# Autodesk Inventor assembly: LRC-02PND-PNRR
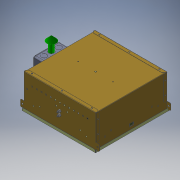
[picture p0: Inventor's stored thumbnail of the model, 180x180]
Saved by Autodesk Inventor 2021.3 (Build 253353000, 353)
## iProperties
load_classification: Lighting
motor: 0 ul
Part Number: LRC-02PND-PNRR
Document SubType Name: Assembly
Designer: JChurch
description: 0:0:Open 2" Pinhole Downlight-COB LED
manufacturer: 0:0:The Kirlin Company
model: 0:0:LRC-02PND
url: 0:0:
Author: JChurch
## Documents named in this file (5)
- X:\Revit Files\0000-Un-Zipped\COB\LRC-02PND-PNR\LRC-02PND-PNRR.iam
- X:\INVENTOR\830\830520-00-00.ipt
- X:\INVENTOR\881\881088-00-00.iam
- X:\INVENTOR\750\750453-02-XX.iam
- X:\Revit Files\0000-Un-Zipped\COB\LRC-02PND-PNR\LRC-02PND-PNRR_Substitute_1.ipt
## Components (4 placed, 4 different names)
1. 830520-00-00:1 — Mate:1, Mate:2, Mate:3, Mate:4, Tangent:1, Angle:1, Insert:1
2. 881088-00-00:1 [sub-assembly] — Mate:4, Tangent:1, Angle:1
3. 750453-02-XX:1 [sub-assembly] — Insert:1
4. LRC-02PND-PNRR_Substitute_1:1
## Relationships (7: Mate 4, Tangent 1, Angle 1, Insert 1)
- Mate:1: 830520-00-00:1
- Mate:2: 830520-00-00:1
- Mate:3: 830520-00-00:1
- Mate:4: 830520-00-00:1 ↔ 881088-00-00:1
- Tangent:1: 830520-00-00:1 ↔ 881088-00-00:1
- Angle:1: 830520-00-00:1 ↔ 881088-00-00:1
- Insert:1: 830520-00-00:1 ↔ 750453-02-XX:1
